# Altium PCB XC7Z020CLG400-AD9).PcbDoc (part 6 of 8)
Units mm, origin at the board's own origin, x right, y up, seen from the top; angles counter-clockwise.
Board outline 38 x 38 mm, 14 copper layers (Top Layer, GND02, ART03, PWR04, ART05, GND06, ART07, ART08, PWR09, ART10, GND11, ART12, PWR13, Bottom Layer); 276 components, 302 nets, 1684 pads, 1576 vias.
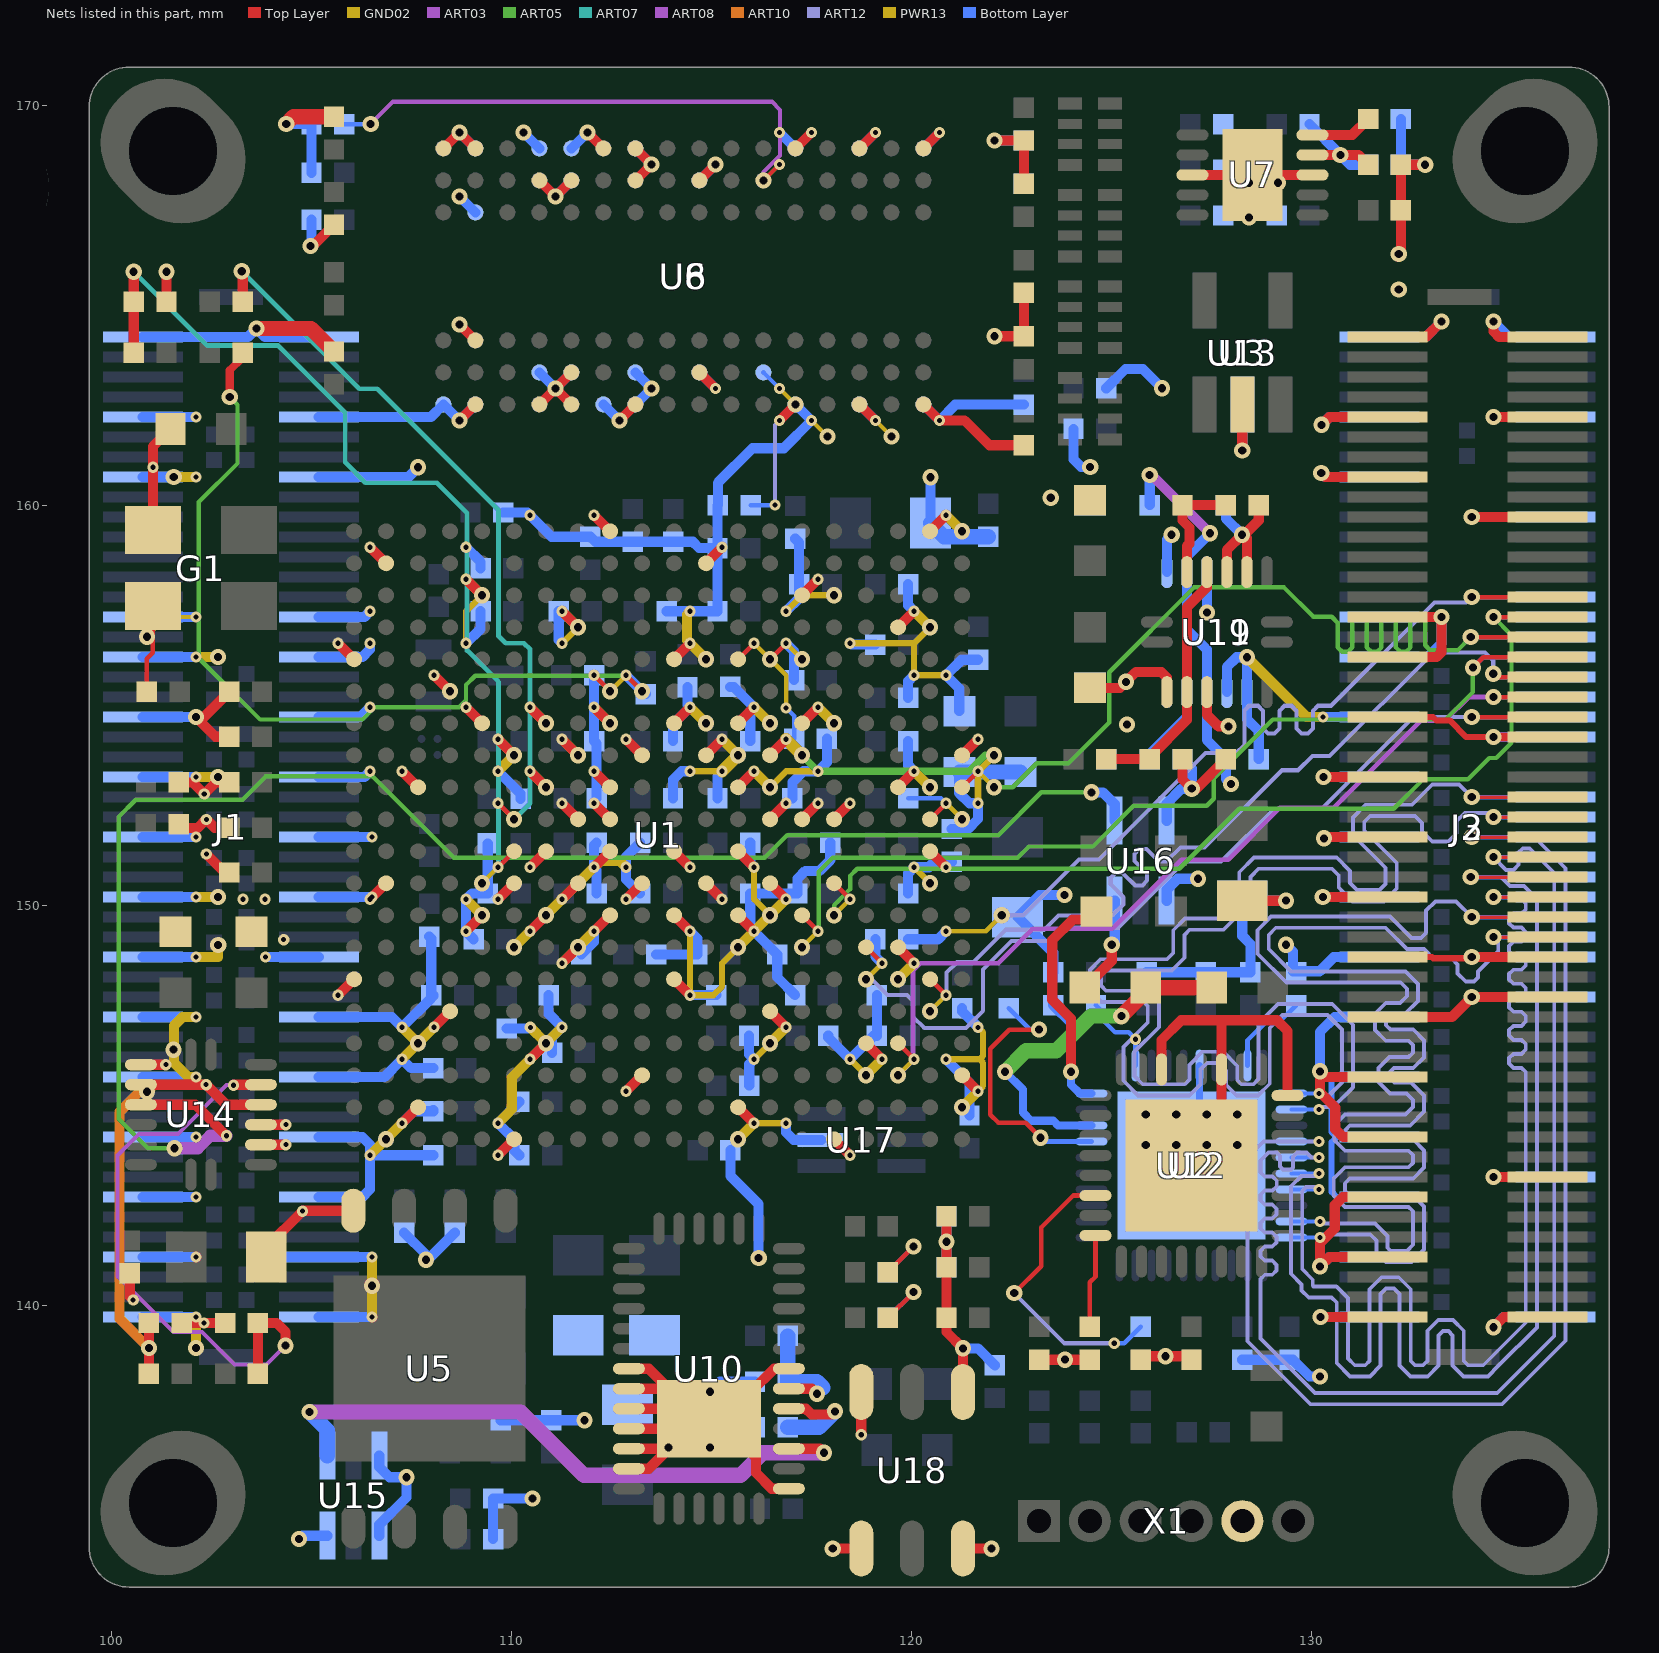
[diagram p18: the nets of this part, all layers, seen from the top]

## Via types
v1: diameter 0.406, hole 0.203, GND02 to PWR13, 466 vias
v2: diameter 0.279, hole 0.127, Top Layer to GND02, tented top, 373 vias
v3: diameter 0.406, hole 0.203, Top Layer to Bottom Layer, 324 vias
v4: diameter 0.279, hole 0.127, PWR13 to Bottom Layer, 207 vias
v5: diameter 0.279, hole 0.127, Top Layer to ART03, tented top, 41 vias
v6: diameter 0.279, hole 0.127, Top Layer to ART03, 40 vias
v7: diameter 0.279, hole 0.127, PWR13 to Bottom Layer, tented bottom, 39 vias
v8: diameter 0.279, hole 0.127, ART12 to Bottom Layer, 30 vias
v9: diameter 0.279, hole 0.127, Top Layer to GND02, 20 vias
v10: diameter 0.406, hole 0.203, Top Layer to Bottom Layer, tented both sides, 16 vias
v11: diameter 0.406, hole 0.203, ART03 to ART12, 11 vias
v12: diameter 0.406, hole 0.203, Top Layer to Bottom Layer, tented top, 9 vias

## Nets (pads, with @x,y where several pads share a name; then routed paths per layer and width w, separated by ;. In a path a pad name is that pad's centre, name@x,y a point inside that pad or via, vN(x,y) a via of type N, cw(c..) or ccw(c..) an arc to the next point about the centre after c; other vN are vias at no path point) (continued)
GND: C2.2 C3.2 C4.2 C5.2 C6.2 C7.2 C8.2 C9.2 C12.2 C13.2 C14.2 C15.2 C16.2 C17.2 C18.2 C19.2 C20.2 C21.2 C22.2 C23.2 C24.1 C25.1 C26.1 C27.1 C28.1 C29.1 C30.2 C31.2 C32.2 C33.2 C37.2 C38.2 C39.2 C40.2 C41.2 C42.2 C43.2 C44.2 C45.2 C46.2 C47.2 C48.2 C49.2 C50.2 C51.2 C52.2 C53.2 C54.2 C55.2 C56.2 C57.2 C58.2 C59.2 C60.2 C61.2 C62.2 C63.2 C64.2 C65.2 C66.2 C67.2 C68.2 C69.2 C70.2 C71.2 C72.2 C73.2 C74.2 C75.2 C76.2 C77.2 C78.2 C79.2 C80.2 C81.2 C93.2 C94.2 C96.1 C97.2 C99.1 C101.2 C102.2 C111.2 C112.2 C113.2 C114.2 C115.2 C116.2 C117.2 C118.2 C119.2 C120.2 C121.2 C122.2 C123.2 C124.2 C125.2 C126.2 C128.2 C129.2 C130.2 C131.2 C132.2 C133.2 C134.2 C135.2 C136.2 C137.2 C138.2 C139.2 C140.2 C144.1 C145.1 C147.2 C148.2 C213.2 C248.1 C249.1 C250.1 C254.2 DONE.2 G1.2 J1.1 J1.5 J1.8 J1.15 J1.17 J1.20 J1.23 J1.26 J1.29 J1.32 J1.35 J1.38 J1.41 J1.44 J1.47 J1.50 J1.51 J1.55 J1.58 J1.65 J1.67 J1.70 J1.73 J1.76 J1.79 J1.82 J1.85 J1.88 J1.91 J1.94 J1.97 J1.100 J2.1 J2.8 J2.17 J2.19 J2.30 J2.41 J2.46 J2.50 J2.51 J2.54 J2.57 J2.60 J2.63 J2.66 J2.69 J2.72 J2.75 J2.78 J2.81 J2.84 J2.86 J2.93 J2.96 J2.100 J3.1 J3.8 J3.17 J3.19 J3.30 J3.41 J3.46 J3.50 J3.51 J3.54 J3.57 J3.60 J3.63 J3.66 J3.69 J3.72 J3.75 J3.78 J3.81 J3.84 J3.86 J3.93 J3.96 J3.100 R1.2 R2.2 R4.2 R8.2 R9.2 R12.2 R15.2 R17.2 R19.2 R20.2 R21.2 R22.2 R26.2 R42.1 R45.2 R52.1 R53.1 R54.1 R55.1 R57.1 R61.2 R64.2 R66.2 R67.2 R68.2 R70.1 R124.1 R135.1 R137.2 R138.2 U1.A8 U1.A18 U1.B1 U1.B11 U1.C4 U1.C9 U1.C14 U1.D17 U1.E10 U1.E20 U1.F3 U1.F7 U1.F10 U1.G10 U1.G12 U1.G16 U1.H7 U1.H9 U1.H11 U1.H13 U1.H19 U1.J2 U1.J8 U1.J12 U1.K5 U1.K7 U1.K11 U1.K13 U1.K15 U1.L8 U1.L12 U1.L18 U1.M1 U1.M7 U1.M9 U1.M10 U1.M11 U1.M13 U1.N4 U1.N8 U1.N10 U1.N12 U1.N14 U1.P7 U1.P9 U1.P11 U1.P13 U1.P17 U1.R8 U1.R12 U1.R20 U1.T3 U1.T7 U1.T13 U1.U6 U1.U16 U1.V9 U1.V19 U1.W2 U1.W12 U1.Y5 U1.Y15 U2.36 U2.41 U3.2 U5.4 U6.A9 U6.B1 U6.B3 U6.B9 U6.D1 U6.D8 U6.E1 U6.E2 U6.E8 U6.F9 U6.G1 U6.G8 U6.G9 U6.J2 U6.J8 U6.M1 U6.M9 U6.P1 U6.P9 U6.T1 U6.T9 U7.3 U7.8 U7.P U8.A9 U8.B1 U8.B3 U8.B9 U8.D1 U8.D8 U8.E1 U8.E2 U8.E8 U8.F9 U8.G1 U8.G8 U8.G9 U8.J2 U8.J8 U8.M1 U8.M9 U8.P1 U8.P9 U8.T1 U8.T9 U10.13 U10.14 U10.15 U10.16 U10.17 U10.18 U10.26 U10.32 U10.39 U11.2 U11.3 U11.9 U12.8 U12.11 U12.14 U12.33 U13.2 U14.2 U14.3 U14.9 U15.3 U15.4 U15.6 U16.3 U16.4 U16.6 U17.2 U18.1 U18.3 U18.4 U18.6 U19.2 U19.3 U19.9 X1.5 | length 463.8
  Top Layer w0.152: J3.69@131.9,148.719 133.018,148.719 133.045,148.692 133.979,148.692 v3(134.007,148.719) ; J3.81@131.9,154.719 133.037,154.719 133.121,154.635 133.452,154.635 133.868,154.219 v3(134.548,154.219)
  Top Layer w0.229: v3(134.548,154.219) J3.30@135.9,154.219
  Top Layer w0.254: C139.2@100.457,140.814 100.457,140.235 v9(100.543,140.149) ; U14.9@100.735,146.03 v9(101.358,146.03) ; G1.2@101.035,159.395 v9(101.035,160.966) 101.035,161.485 C38.2@101.475,161.925 ; DONE.2@101.375,165.1 v3(101.375,165.852) ; C9.2@101.683,151.943 102.151,151.943 v2(102.37,152.163) 102.579,151.954 C148.2@102.943,151.954 C148.2@102.993,151.954 ; C30.2@101.683,153.086 102.032,153.086 v2(102.32,152.798) 102.608,153.086 C32.2@102.943,153.086 ; C140.2@101.756,139.573 v9(102.311,139.573) R12.2@102.841,139.573 ; v2(102.37,151.298) 102.833,150.835 C37.2@102.943,150.835 ; C8.2@102.943,154.229 102.601,154.229 v3(102.111,154.719) 102.309,154.719 C46.2@102.943,155.353 ; U14.2@103.735,144.03 v9(104.358,144.03) ; U14.3@103.735,144.53 v9(104.358,144.53) ; C138.2@103.87,141.224 103.87,141.462 v9(104.775,142.367) 104.788,142.38 U5.4@106.045,142.38 ; v3(104.978,166.497) 105.033,166.497 C55.2@105.562,167.026 ; v2(105.665,147.765) U1.Y15@106.065,148.165 ; v2(105.665,156.565) U1.Y5@106.065,156.165 ; v2(106.465,150.165) U1.W12@106.865,150.565 ; v2(106.465,158.965) U1.W2@106.865,158.565 ; v4(107.265,144.565) U1.V19@107.665,144.965 ; v2(107.265,153.365) U1.V9@107.665,152.965 ; v2(108.065,146.965) U1.U16@108.465,147.365 ; v2(108.065,155.765) v1(108.465,155.365) ; U8.A9@108.3,168.935 v3(108.7,169.335) U8.B9@109.1,168.935 ; v3(108.7,162.135) U8.B1@109.1,162.535 ; v3(108.7,164.535) U8.B3@109.1,164.135 ; v2(108.865,149.365) v1(109.265,149.765) ; v2(108.865,154.965) U1.T7@109.265,154.565 ; v2(108.865,158.165) v1(109.265,157.765) ; v2(109.665,143.765) U1.R20@110.065,144.165 ; v2(109.665,150.165) U1.R12@110.065,150.565 ; v2(109.665,154.165) v1(110.065,153.765) ; v2(110.465,146.165) v1(110.865,146.565) ; v2(110.465,149.365) v1(110.865,149.765) ; v2(110.465,150.965) U1.P11@110.865,151.365 ; v2(110.465,153.365) v1(110.865,152.965) ; v2(110.465,154.965) v1(110.865,154.565) ; U8.D1@110.7,162.535 v3(111.1,162.935) ; U8.D8@110.7,168.135 v3(111.1,167.735) U8.E8@111.5,168.135 ; v2(111.265,148.565) v1(111.665,148.965) ; v2(111.265,150.165) U1.N12@111.665,150.565 ; v2(111.265,152.565) U1.N10@111.665,152.165 ; v2(111.265,154.165) v1(111.665,153.765) ; v2(111.265,157.365) v1(111.665,156.965) ; U8.E1@111.5,162.535 v3(111.1,162.935) ; U8.E2@111.5,163.335 v3(111.1,162.935) ; v3(111.9,169.335) U8.F9@112.3,168.935 ; v4(112.065,149.365) U1.M13@112.465,149.765 ; v4(112.065,150.965) U1.M11@112.465,151.365 ; v2(112.065,152.565) U1.M10@112.465,152.165 ; v2(112.065,153.365) U1.M9@112.465,152.965 ; v4(112.065,154.965) v1(112.465,154.565) ; v2(112.065,159.765) U1.M1@112.465,159.365 ; v3(112.7,162.135) U8.G1@113.1,162.535 ; v2(112.865,145.365) U1.L18@113.265,145.765 ; v2(112.865,150.165) U1.L12@113.265,150.565 ; v2(112.865,154.165) U1.L8@113.265,153.765 ; U10.18@112.935,135.93 113.432,135.93 113.932,136.43 U10.17@112.935,136.43 ; U10.16@112.935,136.93 U10.39@114.445,136.93 ; U10.15@112.935,137.43 U10.39@114.445,137.43 ; U10.14@112.935,137.93 113.93,137.93 113.43,138.43 U10.13@112.935,138.43 ; U8.G8@113.1,168.135 v3(113.5,168.535) U8.G9@113.1,168.935 ; U1.K15@114.065,148.165 v2(114.465,147.765) ; U1.K13@114.065,149.765 v2(114.465,149.365) ; U1.K11@114.065,151.365 v2(114.465,150.965) ; U1.K7@114.065,154.565 v2(114.465,154.965) ; U1.K5@114.065,156.165 v2(114.465,156.565) ; U8.J2@114.7,163.335 v2(115.1,162.935) ; U8.J8@114.7,168.135 v3(115.1,168.535) ; U1.J12@114.865,150.565 v2(115.265,150.165) ; U1.J8@114.865,153.765 v2(115.265,154.165) ; U1.J2@114.865,158.565 v2(115.265,158.965) ; U10.39@114.935,137.175 115.142,137.175 116.116,136.201 116.116,135.82 116.506,135.43 U10.26@116.935,135.43 ; U1.H19@115.665,144.965 v2(116.065,144.565) ; U1.H13@115.665,149.765 v2(116.065,149.365) ; U1.H11@115.665,151.365 v2(116.065,150.965) ; U1.H9@115.665,152.965 v2(116.065,153.365) ; U1.H7@115.665,154.565 v2(116.065,154.965) ; U10.39@115.989,137.852 116.567,138.43 U10.32@116.935,138.43 ; U1.G16@116.465,147.365 v2(116.865,146.965) ; U1.G12@116.465,150.565 v2(116.865,150.165) ; U1.G10@116.465,152.165 v2(116.865,152.565) ; v2(116.7,162.135) U8.M1@117.1,162.535 U8.M1@117.1,162.485 ; U8.M9@117.1,168.935 v2(117.5,169.335) ; U1.F10@117.265,152.165 v2(117.665,152.565) ; U1.F7@117.265,154.565 v2(117.665,154.965) ; U1.F3@117.265,157.765 v2(117.665,158.165) ; v3(118.031,133.931) U18.4@118.745,133.931 ; U1.E20@118.065,144.165 v2(118.465,143.765) ; U1.E10@118.065,152.165 v2(118.465,152.565) ; U8.P1@118.7,162.535 v2(119.1,162.135) ; U8.P9@118.7,168.935 v2(119.1,169.335) ; v9(118.745,136.779) U18.3@118.745,137.849 ; U1.D17@118.865,146.565 v2(119.265,146.165) ; U1.C14@119.665,148.965 v4(120.065,148.565) ; U1.C9@119.665,152.965 v2(120.065,153.365) ; U1.C4@119.665,156.965 v2(120.065,157.365) ; U8.T1@120.3,162.535 v2(120.7,162.135) 121.329,162.135 121.949,161.515 C60.2@122.809,161.515 ; U8.T9@120.3,168.935 v2(120.7,169.335) ; U1.B11@120.465,151.365 v2(120.865,150.965) ; U1.B1@120.465,159.365 v2(120.865,159.765) ; C254.2@120.875,142.24 v3(120.875,141.602) R1.2@120.875,140.97 C25.1@120.875,139.7 120.875,139.348 v3(121.285,138.938) U18.1@121.285,137.849 ; U1.A18@121.265,145.765 v2(121.665,145.365) ; U1.A8@121.265,153.765 v2(121.665,154.165) ; U18.6@121.285,133.931 v3(121.999,133.931) ; v3(122.076,164.24) C56.2@122.809,164.24 C57.2@122.809,165.325 ; v3(122.076,169.135) C59.2@122.809,169.135 C58.2@122.809,168.05 ; R137.2@123.19,138.655 v3(123.837,138.655) R135.1@124.46,138.655 ; C145.1@124.335,147.955 125.006,148.626 v3(125.006,149.028) ; C78.2@124.46,155.45 125.211,155.45 125.61,155.849 126.245,155.849 126.385,155.709 U19.9@126.385,155.345 ; C248.1@125.73,138.655 125.816,138.741 v3(126.352,138.741) 126.914,138.741 C250.1@127,138.655 ; U12.14@126.25,145.91 126.25,146.646 126.746,147.142 127.762,147.142 ; C81.2@126.775,153.67 126.775,153.16 127.007,152.928 127.118,152.928 C80.2@127.86,153.67 ; U12.33@127,143.51 127.75,144.26 U12.11@127.75,145.91 127.75,147.13 127.762,147.142 ; U7.8@127.024,168.275 U7.P@128.524,168.275 U7.3@130.024,168.275 ; U19.3@127.885,158.345 127.885,158.897 v3(128.266,159.278) v3@128.308,159.278 ; C79.2@128.27,150.13 v3(129.365,150.13) ; v3(128.27,161.385) U3.2@128.27,162.53 ; U19.2@128.385,158.345 128.385,159.201 v3@128.308,159.278 ; R26.2@128.68,160.02 128.68,159.643 128.315,159.278 v3@128.308,159.278 ; U12.8@129.4,145.26 129.4,146.876 129.134,147.142 127.762,147.142 ; v10(130.224,139.719) J3.51@131.9,139.719 ; v3(130.251,162.027) 130.444,162.219 J3.96@131.9,162.219 ; v3(130.284,150.219) J3.72@131.9,150.219 ; v3(130.301,153.219) J3.78@131.9,153.219 ; v3(130.314,151.689) 130.344,151.719 J3.75@131.9,151.719 ; v3@130.345,160.719 J3.93@131.9,160.719 ; J3.54@131.9,141.219 130.444,141.219 v3(130.213,140.988) 130.213,141.567 130.581,141.935 130.581,142.519 130.781,142.719 J3.57@131.9,142.719 ; J3.60@131.9,144.219 130.792,144.219 130.594,144.417 130.594,144.958 130.213,145.339 v3(130.213,145.864) 130.358,145.719 J3.63@131.9,145.719 ; J3.66@131.9,147.219 133.507,147.219 v3(134.007,147.719) J3.17@135.9,147.719 ; J3.84@131.9,156.219 133.125,156.219 133.248,156.343 v3(133.248,157.219) J3.86@131.9,157.219 ; J3.100@131.9,164.219 132.857,164.219 v10(133.248,164.61) ; v3@132.169,166.233 v3@132.178,166.224 ; v3@132.236,166.309 C97.2@132.236,167.386 C96.1@132.236,168.529 v3(132.842,168.529) ; v3(134.007,148.719) J3.19@135.9,148.719 ; v3(134.007,159.719) J3.41@135.9,159.719 ; v10(134.548,139.465) 134.802,139.719 J3.1@135.9,139.719 ; v3(134.548,143.219) J3.8@135.9,143.219 ; v10(134.548,162.219) J3.46@135.9,162.219 ; v10(134.548,164.61) 134.548,164.359 134.688,164.219 J3.50@135.9,164.219
  Top Layer w0.381: v3(103.624,164.435) 104.986,164.435 C99.1@105.562,163.859 ; v3(104.369,169.545) 104.554,169.73 C69.2@105.562,169.73
  GND02 w0.152: v2(108.865,149.365) v1(109.265,149.765)
  GND02 w0.254: v1(106.865,144.165) v4(107.265,144.565) ; v1(107.665,146.565) v2(108.065,146.965) ; v2(108.865,158.165) v1(109.265,157.765) ; v2(109.665,154.165) v1(110.065,153.765) ; v1(110.065,148.965) v2(110.465,149.365) ; v2(110.465,146.165) v1(110.865,146.565) ; v2(110.465,153.365) v1(110.865,152.965) ; v2(110.465,154.965) v1(110.865,154.565) ; v1(110.865,149.765) v2(111.265,150.165) ; v2(111.265,148.565) v1(111.665,148.965) v4(112.065,149.365) ; v2(111.265,154.165) v1(111.665,153.765) ; v2(111.265,157.365) v1(111.665,156.965) ; v2(115.265,154.165) v1(115.665,153.765) ; v1(115.665,144.165) v2(116.065,144.565) ; v1(115.665,148.965) v2(116.065,149.365) ; v2(116.065,153.365) v1(116.465,152.965) ; v2(116.065,154.965) v1(116.465,154.565) ; v1(116.465,146.565) v2(116.865,146.965) ; v1(116.465,149.765) v2(116.865,150.165) ; v2(117.665,154.965) v1(118.065,154.565) ; v1(118.865,145.765) v2(119.265,146.165) ; v1(119.665,148.165) v4(120.065,148.565) ; v2(120.065,153.365) v1(120.465,152.965) ; v2(120.065,157.365) v1(120.465,156.965) ; v2(120.865,159.765) v1(121.265,159.365) ; v1(121.265,144.965) v2(121.665,145.365)
  PWR13 w0.102: v1(100.885,156.73) 101.375,157.219 v4(102.111,157.219)
  PWR13 w0.114: v7(117.5,162.135) v1(117.9,161.735) ; v2(119.1,162.135) v1(119.5,161.735)
  PWR13 w0.152: v4(108.865,156.565) 108.865,157.365 v1(109.265,157.765) ; v4(111.265,156.565) v1(111.665,156.965) ; v2(114.465,149.365) v2(114.465,147.765) 115.05,147.765 115.265,147.98 115.265,148.565 v1(115.665,148.965) ; v4(114.465,153.365) v4(115.265,153.365) ; v1(115.665,144.165) v2(116.065,144.565) v4(116.865,144.565) ; v4(116.065,146.165) v1(116.465,146.565) ; v2(116.065,150.965) 116.065,150.165 v1(116.465,149.765) ; v1(116.465,152.965) 116.865,153.365 v4(117.665,153.365) ; v4(116.865,157.365) 117.265,157.765 v1(118.065,157.765) ; v4(118.465,146.165) v1(118.865,145.765) ; v4(118.465,156.565) 120.065,156.565 ; v4(120.065,150.965) v1(120.465,150.565) ; v2(120.065,157.365) v1(120.465,156.965) 120.065,156.565 ; v4(120.865,146.165) 121.705,146.165 ; v4(120.865,155.765) v4(120.065,155.765) 120.065,156.565 ; v1(121.265,144.965) 121.793,145.493 121.793,146.077 121.705,146.165 ; v4(121.666,146.964) 121.793,146.837 121.793,146.253 121.705,146.165
  PWR13 w0.254: v1(101.557,160.719) v4(102.111,160.719) ; v4(102.111,139.719) 102.111,138.947 v1(102.114,138.944) ; v4(102.111,145.719) 101.924,145.719 101.559,146.085 101.559,147.007 101.771,147.219 v4(102.111,147.219) ; v4(102.111,148.719) 102.665,148.719 102.667,148.721 v1(102.667,149.022) ; v4(102.111,150.219) v1(102.665,150.219) ; v4(102.111,153.219) v1(102.665,153.219) ; v4(102.111,156.219) v1(102.665,156.219) ; v4(106.465,143.765) v1(106.865,144.165) v4(107.265,144.565) ; v4(106.511,139.719) v1(106.511,140.504) v4(106.511,141.219) ; v4(107.265,146.165) v1(107.665,146.565) v4(107.265,146.965) ; v4(108.865,150.165) v1(109.265,149.765) ; v4(109.665,144.565) 110.007,144.907 110.007,145.707 v1(110.865,146.565) ; v4(109.665,153.365) v1(110.065,153.765) ; v4(110.471,146.964) 110.865,146.571 v1(110.865,146.565) ; v1(110.865,149.765) v4(112.065,150.965) 112.23,151.13 112.7,151.13 v4(112.865,150.965) ; v4@111.221,146.921 v4(111.265,146.965) v1(110.865,146.565) ; v1(111.665,148.965) v4(112.065,149.365) ; v4(112.065,154.965) v1(112.465,154.565) ; v2(114.465,154.965) v1(114.865,154.565) ; v4(114.465,157.365) 114.388,157.288 114.388,156.642 v1(114.865,156.165) ; v1(115.665,148.965) v2(116.065,149.365) v1(116.465,149.765) ; v2(116.065,154.965) v1(116.465,154.565) ; v1(119.665,148.165) v4(120.065,148.565) ; v2(120.065,153.365) v1(120.465,152.965) ; v3(128.385,156.217) 129.883,154.719 v4(130.284,154.719)
  PWR13 w0.305: v4(115.265,153.365) v1(115.665,153.765)
  Bottom Layer w0.114: v3@134.523,154.219 v3(134.548,154.219)
  Bottom Layer w0.152: 130.505,145.618 130.505,144.344 130.63,144.219 ; J2.57@131.7,142.719 130.636,142.719 130.505,142.85 130.505,144.094 130.63,144.219 ; J2.60@131.7,144.219 130.63,144.219
  Bottom Layer w0.178: U2.41@127.2,143.71 U2.36@127.2,146.01
  Bottom Layer w0.229: v10@134.523,139.465 134.777,139.719 J2.1@136.1,139.719
  Bottom Layer w0.254: J1.50@100.782,139.719 v4(102.111,139.719) ; J1.47@100.782,141.219 v4(102.111,141.219) ; J1.44@100.782,142.719 v4(102.111,142.719) ; J1.41@100.782,144.219 v4(102.111,144.219) ; J1.38@100.782,145.719 v4(102.111,145.719) ; J1.35@100.782,147.219 v4(102.111,147.219) ; J1.32@100.782,148.719 v4(102.111,148.719) ; J1.29@100.782,150.219 v4(102.111,150.219) ; J1.26@100.782,151.719 v4(102.111,151.719) ; J1.23@100.782,153.219 v4(102.111,153.219) ; J1.20@100.782,154.719 v3(102.111,154.719) ; J1.17@100.782,156.219 v4(102.111,156.219) ; J1.15@100.782,157.219 v4(102.111,157.219) ; J1.8@100.782,160.719 v4(102.111,160.719) ; J1.5@100.782,162.219 v4(102.111,162.219) ; J1.1@100.782,164.219 103.408,164.219 v3(103.624,164.435) 103.84,164.219 J1.51@105.182,164.219 ; v4(103.848,148.719) J1.82@105.182,148.719 ; v3(104.369,169.545) R66.2@105,169.545 C75.2@105,168.326 ; J1.97@104.376,141.219 J1.97@105.182,141.219 v4(106.511,141.219) ; v3(104.686,134.169) 104.772,134.255 U15.6@105.395,134.255 ; v3(104.978,166.497) 105,166.519 C102.2@105,167.157 ; J1.100@105.182,139.719 v4(106.511,139.719) ; J1.94@105.182,142.719 106.27,142.719 106.465,142.914 v4(106.465,143.765) ; J1.91@105.182,144.219 106.276,144.219 106.465,144.03 v4(106.465,143.765) ; J1.88@105.182,145.719 106.819,145.719 v4(107.265,146.165) 107.487,145.943 C23.2@108.045,145.943 ; J1.85@105.182,147.219 107.011,147.219 v4(107.265,146.965) 107.994,147.694 C22.2@107.994,147.765 107.994,149.184 R124.1@107.946,149.233 ; J1.79@105.182,150.219 v4(106.511,150.219) ; J1.76@105.182,151.719 v4(106.511,151.719) ; J1.73@105.182,153.219 106.319,153.219 v4(106.465,153.365) ; J1.70@105.182,154.719 106.219,154.719 v4(106.465,154.965) ; J1.67@105.182,156.219 106.271,156.219 106.465,156.413 v4(106.465,156.565) ; J1.65@105.182,157.219 106.319,157.219 v4(106.465,157.365) ; J1.58@105.182,160.719 107.418,160.719 v3(107.665,160.966) ; J1.55@105.182,162.219 107.984,162.219 U6.A9@108.3,162.535 v3(108.7,162.135) U6.B9@109.1,162.535 ; U15.4@106.695,134.255 106.695,134.527 107.376,135.208 v3(107.376,135.716) 106.949,135.716 106.695,135.97 U15.3@106.695,136.255 ; v4(107.265,144.565) 107.564,144.864 C19.2@108.012,144.864 ; R55.1@107.315,141.83 v3@107.861,141.284 ; v3(107.861,141.154) 107.909,141.154 R54.1@108.585,141.83 ; C21.2@108.045,143.765 v4(106.465,143.765) ; C19.2@108.045,144.864 C19.2@108.012,144.864 ; C19.2@108.045,144.897 C19.2@108.012,144.864 ; C22.2@108.045,147.745 C22.2@108.045,147.765 ; v3(108.7,167.735) U6.B3@109.1,167.335 ; v3(108.7,169.335) U6.B1@109.1,168.935 ; v4@108.849,158.965 v4(108.865,158.965) 109.229,158.601 C62.2@109.229,158.437 ; v4(108.865,156.565) 109.229,156.929 C6.2@109.229,157.365 ; C45.2@109.054,149.164 108.865,149.353 v4(108.865,150.165) 109.009,150.309 C43.2@109.407,150.309 C33.2@109.407,151.562 ; R57.1@109.541,134.169 R53.1@109.541,135.185 v3(110.528,135.185) ; v4(109.665,153.365) 110.227,152.803 C31.2@110.227,152.678 ; C24.1@109.728,137.14 C48.2@110.998,137.14 v3(111.826,137.14) ; C68.2@109.795,159.834 110.396,159.834 v4(110.465,159.765) 111.002,159.228 R68.2@111.973,159.228 112.099,159.102 C64.2@113.03,159.102 C74.2@114.046,159.102 114.532,159.102 114.689,158.945 C71.2@115.151,158.945 ; C51.2@109.88,146.935 110.442,146.935 v4(110.471,146.964) ; C20.2@110.195,143.765 110.068,143.892 110.068,144.162 v4(109.665,144.565) 109.665,144.572 C18.2@110.195,145.102 ; v3(110.3,169.335) U6.D1@110.7,168.935 ; U6.D8@110.7,163.335 v3(111.1,162.935) U6.E8@111.5,163.335 ; C13.2@110.928,147.765 110.928,147.302 v4(111.265,146.965) 111.015,146.715 C41.2@111.015,146.325 ; v3(111.1,167.735) U6.E2@111.5,168.135 ; C5.2@111.182,157.365 111.182,156.648 v4(111.265,156.565) ; U6.E1@111.5,168.935 v3(111.9,169.335) ; C47.2@111.748,148.785 112.065,149.102 v4(112.065,149.365) ; C66.2@112.065,155.765 v4(112.065,154.965) C112.2@112.065,154.119 112.129,154.055 C121.2@112.129,152.692 ; C120.2@112.129,150.309 112.129,150.901 v4(112.065,150.965) 112.065,151.515 C124.2@112.129,151.579 ; U6.F9@112.3,162.535 v3(112.7,162.135) ; U6.G9@113.1,162.535 v3(113.5,162.935) U6.G8@113.1,163.335 ; U6.G1@113.1,168.935 v3(113.5,168.535) ; C123.2@113.217,150.309 112.865,150.661 112.865,151.227 C122.2@113.217,151.579 ; C44.2@113.618,148.785 C72.2@114.644,148.785 114.644,149.186 v2(114.465,149.365) ; C61.2@113.878,157.365 C70.2@115.151,157.365 C71.2@115.151,158.945 ; C119.2@114.037,152.692 114.037,153.153 114.249,153.365 v4(114.465,153.365) ; C113.2@114.037,154.119 114.037,154.537 v2(114.465,154.965) 114.402,155.028 C76.2@114.402,155.466 ; v2(114.465,147.765) 114.469,147.769 C39.2@115.119,147.769 ; U6.J8@114.7,163.335 v2(115.1,162.935) ; U6.J2@114.7,168.135 v3(115.1,168.535) ; v3(114.959,136.455) 115.579,136.455 C135.2@116.087,136.963 ; v3(114.959,137.852) 115.213,138.106 R9.2@116.087,138.106 ; C118.2@115.151,152.692 115.151,153.251 v4(115.265,153.365) ; C49.2@115.468,155.473 115.557,155.473 v2(116.065,154.965) 115.971,154.871 C54.2@115.971,154.119 ; C14.2@115.472,143.891 115.472,143.252 116.18,142.545 v3(116.18,141.199) ; C40.2@115.939,146.753 115.939,146.291 v4(116.065,146.165) 115.943,146.043 C12.2@115.943,145.507 ; C117.2@115.971,151.579 115.971,151.059 v2(116.065,150.965) ; v7(116.7,169.335) U6.M1@117.1,168.935 ; v4(116.865,144.565) 116.865,144.337 117.058,144.145 U17.2@117.745,144.145 ; v4(116.865,157.365) 117.192,157.692 C67.2@117.192,158.045 117.192,159.08 C7.2@117.094,159.178 ; R45.2@117.024,152.692 117.024,153.092 117.297,153.365 v4(117.665,153.365) 117.885,153.585 R70.1@117.885,154.178 ; C17.2@117.09,147.769 116.662,148.197 116.662,148.209 116.643,148.228 C42.2@116.643,148.785 116.065,149.363 v2(116.065,149.365) 115.971,149.459 C114.2@115.971,150.309 C213.2@117.151,150.309 117.151,150.679 117.348,150.876 117.704,150.876 117.971,151.143 C115.2@117.971,151.579 ; U6.M9@117.1,162.535 v7(117.5,162.135) 116.807,161.442 116.027,161.442 115.16,160.575 R61.2@115.16,160.02 115.151,160.011 C71.2@115.151,158.945 ; C15.2@117.92,146.753 117.92,146.71 v4(118.465,146.165) 119.053,146.753 R20.2@119.136,146.753 C16.2@119.136,147.769 ; v4(118.465,156.565) 118.498,156.532 R67.2@119.097,156.532 ; U6.P9@118.7,162.535 v2(119.1,162.135) ; U6.P1@118.7,168.935 v2(119.1,169.335) ; R22.2@119.917,150.309 119.917,150.817 v4(120.065,150.965) 120.434,150.965 120.57,151.101 C126.2@121.006,151.101 ; R42.1@119.917,154.119 119.917,153.513 v2(120.065,153.365) ; R52.1@119.917,155.199 119.917,155.617 v4(120.065,155.765) ; C50.2@119.917,158.045 119.917,157.513 v2(120.065,157.365) ; U6.T9@120.3,162.535 v2(120.7,162.135) 121.096,162.531 C73.2@122.809,162.531 ; U6.T1@120.3,168.935 v2(120.7,169.335) ; C53.2@120.475,159.569 v3(120.475,160.715) ; v4(120.865,146.165) 121.451,145.579 R4.2@121.451,144.761 ; R2.2@120.875,140.97 v3(120.875,141.602) C144.1@120.875,142.24 ; C125.2@121.196,154.868 121.196,155.434 v4(120.865,155.765) 121.255,156.155 C63.2@121.665,156.155 ; R19.2@121.265,147.444 121.265,147.365 v4(121.666,146.964) ; v3(121.285,138.938) 121.663,138.938 C249.1@122.085,138.516 ; v3(122.076,169.135) C4.2@122.809,169.135 C52.2@122.809,168.05 ; C28.1@123.546,148.34 123.546,148.827 C116.2@122.653,149.72 123.206,150.273 v3(123.825,150.273) ; C147.2@124.05,161.925 124.05,161.167 124.245,160.972 v3(124.467,160.972) ; C65.2@124.87,162.941 125.353,163.424 125.781,163.424 v3(126.263,162.941) ; v3(125.006,149.028) 125.08,149.102 U16.6@125.08,150.13 ; R15.2@125.882,148.34 R17.2@127.356,148.34 C26.1@128.473,148.34 128.473,149.047 128.27,149.25 C132.2@128.27,150.13 v3(129.365,150.13) ; U16.4@126.38,150.13 126.38,150.402 126.657,150.679 v3(127.165,150.679) ; U16.3@126.38,152.13 126.38,152.561 126.747,152.928 127.007,152.928 127.007,153.438 R8.2@126.775,153.67 ; U11.9@126.385,158.345 126.385,159.158 v3(126.505,159.278) ; U2.41@127,143.51 U2.41@127.2,143.71 ; C133.2@127.86,160.02 127.86,159.684 v3(128.266,159.278) ; U11.3@127.885,155.345 127.885,155.971 128.131,156.217 v3(128.385,156.217) U11.2@128.385,155.345 128.385,154.666 128.68,154.371 C134.2@128.68,153.67 ; C29.1@128.27,138.655 C27.1@129.451,138.655 129.532,138.655 129.954,138.233 v3(130.213,138.233) ; v3(128.27,161.385) U13.2@128.27,162.53 ; v3(129.365,149.028) 129.54,148.853 129.54,148.365 130.204,148.365 130.558,148.719 J2.69@131.7,148.719 ; v3(130.213,140.988) 130.444,141.219 J2.54@131.7,141.219 ; v10(130.224,139.719) J2.51@131.9,139.719 ; v3(130.243,160.821) 130.345,160.719 J2.93@131.7,160.719 ; v3(130.251,162.027) 130.444,162.219 J2.96@131.7,162.219 ; v3(130.284,150.219) J2.72@131.7,150.219 ; v4(130.284,154.719) J2.81@131.7,154.719 ; v3(130.301,153.219) J2.78@131.7,153.219 ; v3(130.314,151.689) 130.344,151.719 J2.75@131.7,151.719 ; J2.63@131.7,145.719 130.358,145.719 v3(130.213,145.864) 130.213,146.85 130.582,147.219 J2.66@131.7,147.219 ; J2.84@131.7,156.219 132.902,156.219 133.248,156.566 v3(133.248,157.219) J2.86@131.7,157.219 ; J2.100@131.7,164.219 132.857,164.219 v10(133.248,164.61) ; R138.2@132.236,169.672 R64.2@132.236,168.529 v3(132.842,168.529) ; v3(134.007,147.719) J2.17@136.1,147.719 ; v3(134.007,148.719) J2.19@136.1,148.719 ; v3(134.007,159.719) J2.41@136.1,159.719 ; v3@134.523,143.219 J2.8@136.1,143.219 ; v3(134.548,154.219) J2.30@136.1,154.219 ; v10(134.548,162.219) J2.46@136.1,162.219 ; v10(134.548,164.61) 134.939,164.219 J2.50@136.1,164.219
  Bottom Layer w0.381: C53.2@120.475,159.569 120.815,159.229 C101.2@121.92,159.229
  other v1: 101.549,146.406
  other v2: 107.265,144.565 120.065,148.565 112.065,149.365 112.065,150.965 112.065,154.965
  other v3: 113.93,136.455 127.007,152.93 125.387,154.534 123.482,160.204 132.181,165.411 132.181,166.3 128.435,167.208 128.435,168.078 129.159,168.078
  other v4: 114.465,147.765 114.465,149.365 116.065,149.365 116.065,150.965 120.065,153.365 114.465,154.965 116.065,154.965 120.065,157.365
  other v7: 119.1,162.135 120.7,162.135 115.1,162.935 119.1,169.335 120.7,169.335
  other v9: 104.305,149.155 103.289,150.165 103.835,150.165
  other v10: 125.362,155.601
  other v12: 125.857,144.018 126.619,144.018 127.381,144.018 128.143,144.018 125.857,144.78 126.619,144.78 127.381,144.78 128.143,144.78
MDIN0: J2.26 J3.26 U2.2 | length 34.8
  Top Layer w0.089: v3(134.548,152.219) J3.26@135.9,152.219
  ART12 w0.097: v8(130.188,144.91) 130.248,144.97 130.545,144.97 131.039,145.464 131.039,147.029 130.519,147.549 129.159,147.549 128.676,147.066 128.676,145.669 128.549,145.542 128.245,145.542 128.143,145.644 128.143,145.999 127.787,146.355 127.279,146.355 126.949,146.025 126.949,145.658 126.833,145.542 125.781,145.542 125.578,145.745 125.578,146.355 126.187,146.964 126.187,147.614 125.922,147.879 124.866,147.879 124.739,148.006 124.739,148.285 124.841,148.387 126.506,148.387 126.822,148.703 126.822,149.276 126.949,149.403 127.802,149.403 128.473,150.074 128.473,150.724 128.676,150.927 130.516,150.927 130.683,150.76 130.683,150.455 131.024,150.114 131.815,150.114 132.131,150.43 132.131,151.068 131.318,151.881 131.318,152.095 131.47,152.248 132.588,152.248 132.766,152.07 132.766,151.867 133.02,151.613 133.426,151.613 133.629,151.816 133.629,152.121 133.833,152.324 134.444,152.324 v3(134.548,152.219)
  Bottom Layer w0.089: U2.2@129.5,144.91 v8(130.188,144.91) v8@130.213,144.91
  Bottom Layer w0.114: v3(134.548,152.219) J2.26@136.1,152.219
MDIN1: J2.24 J3.24 U2.5 | length 34.9
  Top Layer w0.089: v3(134.548,151.219) J3.24@135.9,151.219
  ART12 w0.097: v8(130.188,143.71) 130,143.71 129.88,143.831 129.642,143.831 129.54,143.729 129.54,143.459 129.489,143.408 129.286,143.408 129.21,143.485 129.21,143.754 129.134,143.831 128.921,143.831 128.727,143.637 128.727,143.338 128.832,143.233 129.027,143.233 129.133,143.128 129.133,142.988 129.027,142.883 128.832,142.883 128.727,142.777 128.727,142.637 128.832,142.532 129.02,142.532 129.125,142.427 129.125,142.287 129.02,142.182 128.832,142.182 128.727,142.076 128.727,141.936 128.832,141.831 129.02,141.831 129.125,141.726 129.125,141.586 129.02,141.481 128.832,141.481 128.727,141.375 128.727,141.235 128.832,141.13 129.02,141.13 129.125,141.025 129.125,140.885 129.02,140.779 128.832,140.779 128.727,140.674 128.727,139.181 130.088,137.82 134.645,137.82 136.068,139.243 136.068,150.825 135.458,151.435 135.28,151.435 135.179,151.333 135.179,151.028 135.052,150.901 134.866,150.901 v3(134.548,151.219)
  Bottom Layer w0.089: U2.5@129.5,143.71 v8(130.188,143.71)
  Bottom Layer w0.114: v3@134.523,151.219 v3(134.548,151.219) J2.24@136.1,151.219
MDIN2: J2.22 J3.22 U2.7 | length 34.7
  Top Layer w0.089: v3(134.548,150.219) J3.22@135.9,150.219
  ART12 w0.097: 129.794,142.9 129.769,142.875 ; v8(130.188,142.91) 130.127,142.97 129.864,142.97 129.769,142.875 ; v3(134.548,150.219) 135.201,150.219 135.357,150.063 135.357,149.911 135.251,149.806 135.046,149.806 134.941,149.7 134.941,149.56 135.046,149.455 135.251,149.455 135.357,149.35 135.357,149.21 135.251,149.105 135.046,149.105 134.941,148.999 134.941,148.859 135.046,148.754 135.251,148.754 135.357,148.649 135.357,148.509 135.251,148.404 135.046,148.404 134.941,148.298 134.941,148.158 135.046,148.053 135.251,148.053 135.357,147.948 135.357,147.808 135.251,147.703 135.046,147.703 134.941,147.597 134.941,147.457 135.046,147.352 135.251,147.352 135.357,147.247 135.357,147.107 135.251,147.001 135.046,147.001 134.941,146.896 134.941,146.756 135.046,146.651 135.251,146.651 135.357,146.546 135.357,146.406 135.251,146.3 135.046,146.3 134.941,146.195 134.941,146.055 135.046,145.95 135.251,145.95 135.357,145.845 135.357,139.579 134.293,138.515 133.915,138.515 133.808,138.622 133.808,139.378 133.537,139.649 133.169,139.649 132.898,139.378 132.898,138.622 132.791,138.515 132.588,138.515 132.481,138.622 132.481,140.417 132.182,140.716 131.75,140.716 131.451,140.417 131.451,138.622 131.343,138.515 131.081,138.515 130.912,138.684 130.912,140.197 130.621,140.487 130.048,140.487 130.033,140.503 130.033,140.654 129.769,140.918 129.769,142.875
  Bottom Layer w0.089: U2.7@129.5,142.91 v8(130.188,142.91) v8@130.213,142.91
  Bottom Layer w0.114: v3@134.523,150.219 v3(134.548,150.219) J2.22@136.1,150.219
MDIN3: J2.20 J3.20 U2.10 | length 34.7
  Top Layer w0.089: v3(134.548,149.219) J3.20@135.9,149.219
  ART12 w0.097: v8(130.213,141.71) 130.286,141.783 131.47,141.783 131.623,141.63 131.623,141.337 131.863,141.097 132.501,141.097 132.817,141.413 132.817,142.483 132.546,142.754 130.955,142.754 130.835,142.873 130.835,143.065 130.955,143.185 132.546,143.185 132.817,143.456 132.817,143.887 132.546,144.158 130.955,144.158 130.848,144.265 130.848,144.401 130.955,144.508 132.469,144.508 132.817,144.856 132.817,145.263 132.492,145.587 132.074,145.587 131.953,145.709 131.953,145.833 132.063,145.943 132.546,145.943 132.817,146.214 132.817,146.637 132.546,146.908 131.971,146.908 131.864,147.015 131.864,147.186 131.971,147.293 132.333,147.293 132.664,147.625 132.664,148.045 132.348,148.361 129.489,148.361 128.93,148.92 128.93,149.276 129.108,149.454 131.851,149.454 132.385,148.92 132.817,148.92 133.071,148.666 133.528,148.666 133.655,148.539 133.655,148.311 133.858,148.107 134.061,148.107 134.163,148.209 134.163,148.361 134.671,148.869 134.671,149.097 v3(134.548,149.219)
  Bottom Layer w0.089: U2.10@129.5,141.71 v8(130.213,141.71)
  Bottom Layer w0.114: v3(134.548,149.219) J2.20@136.1,149.219
MDIP0: J2.27 J3.27 U2.1 | length 34.8
  Top Layer w0.089: v3(134.007,152.719) J3.27@135.9,152.719
  ART12 w0.097: v8(130.188,145.31) 130.248,145.25 130.429,145.25 130.759,145.58 130.759,146.914 130.404,147.269 129.275,147.269 128.956,146.95 128.956,145.553 128.665,145.263 128.129,145.263 127.864,145.528 127.864,145.883 127.672,146.075 127.395,146.075 127.229,145.909 127.229,145.542 126.949,145.263 125.665,145.263 125.298,145.629 125.298,146.471 125.908,147.08 125.908,147.498 125.806,147.599 124.751,147.599 124.46,147.89 124.46,148.401 124.725,148.666 126.39,148.666 126.543,148.819 126.543,149.392 126.833,149.682 127.686,149.682 128.194,150.19 128.194,150.839 128.561,151.206 130.632,151.206 130.962,150.876 130.962,150.571 131.14,150.393 131.699,150.393 131.851,150.546 131.851,150.952 131.039,151.765 131.039,152.211 131.355,152.527 132.512,152.527 133.02,153.035 133.691,153.035 v3(134.007,152.719)
  Bottom Layer w0.089: U2.1@129.5,145.31 v8(130.188,145.31) v8@130.213,145.31
  Bottom Layer w0.114: v3(134.007,152.719) J2.27@136.1,152.719
MDIP1: J2.25 J3.25 U2.4 | length 35
  Top Layer w0.089: v3(134.007,151.719) J3.25@135.9,151.719
  ART12 w0.097: v8(130.188,144.11) 128.805,144.11 128.397,143.702 128.397,139.116 129.972,137.541 134.761,137.541 136.347,139.127 136.347,150.941 135.569,151.719 v3(134.007,151.719)
  Bottom Layer w0.089: U2.4@129.5,144.11 v8(130.188,144.11) v8@130.213,144.11
  Bottom Layer w0.114: v3(134.007,151.719) J2.25@136.1,151.719
MDIP2: J2.23 J3.23 U2.6 | length 34.8
  Top Layer w0.089: v3@134.007,150.719 J3.23@135.9,150.719
  ART12 w0.097: v8(130.188,143.31) 130.127,143.25 129.748,143.25 129.489,142.991 129.489,140.802 129.753,140.538 129.753,140.387 129.932,140.208 130.505,140.208 130.632,140.081 130.632,138.568 130.965,138.235 131.459,138.235 131.73,138.506 131.73,140.301 131.866,140.437 132.066,140.437 132.201,140.301 132.201,138.506 132.472,138.235 132.907,138.235 133.178,138.506 133.178,139.263 133.285,139.37 133.421,139.37 133.528,139.263 133.528,138.506 133.799,138.235 134.409,138.235 134.679,138.506 135.636,139.463 135.636,150.179 135.316,150.499 134.961,150.499 134.74,150.719 v3(133.982,150.719)
  Bottom Layer w0.089: U2.6@129.5,143.31 v8(130.188,143.31) v8@130.213,143.31
  Bottom Layer w0.114: v3@134.007,150.719 J2.23@136.1,150.719
MDIP3: J2.21 J3.21 U2.9 | length 34.7
  Top Layer w0.089: v3(134.007,149.719) J3.21@135.9,149.719
  ART12 w0.097: v8(130.213,142.11) 130.261,142.062 131.586,142.062 131.902,141.746 131.902,141.453 131.978,141.376 132.385,141.376 132.537,141.529 132.537,142.367 132.43,142.474 130.84,142.474 130.556,142.758 130.556,143.181 130.84,143.464 132.43,143.464 132.537,143.571 132.537,143.771 132.43,143.878 130.84,143.878 130.569,144.149 130.569,144.517 130.84,144.788 132.353,144.788 132.537,144.972 132.537,145.147 132.376,145.308 131.959,145.308 131.674,145.593 131.674,145.948 131.947,146.222 132.43,146.222 132.537,146.329 132.537,146.522 132.43,146.629 131.856,146.629 131.585,146.899 131.585,147.302 131.856,147.573 132.217,147.573 132.385,147.741 132.385,147.93 132.232,148.082 129.373,148.082 128.651,148.804 128.651,149.392 128.992,149.733 131.967,149.733 132.501,149.2 132.74,149.2 132.867,149.327 132.867,149.885 133.096,150.114 133.612,150.114 v3(134.007,149.719) v3@134.019,149.708
  Bottom Layer w0.089: U2.9@129.5,142.11 v8(130.213,142.11)
  Bottom Layer w0.114: v3(134.007,149.719) J2.21@136.1,149.719
MMC-CLK: J2.37 J3.37 R24.2 | length 24.3
  Top Layer w0.114: v3(134.007,157.719) J3.37@135.9,157.719
  ART12 w0.102: v1(122.257,149.765) 122.79,149.765 124.185,151.159 124.693,151.159 127.356,153.822 128.118,153.822 128.321,154.026 128.321,154.889 128.435,155.004 128.659,155.004 128.784,154.878 128.784,154.431 128.91,154.305 129.078,154.305 129.203,154.431 129.203,154.878 129.329,155.004 129.497,155.004 129.623,154.878 129.623,154.431 129.748,154.305 129.916,154.305 130.042,154.431 130.042,154.878 130.167,155.004 130.251,155.004 130.493,155.004 133.071,157.582 133.869,157.582 v3(134.007,157.719)
  PWR13 w0.114: v4(120.865,149.365) 121.857,149.365 v1(122.257,149.765)
  Bottom Layer w0.114: v3(134.007,157.719) J2.37@136.1,157.719
  Bottom Layer w0.254: R24.2@119.917,149.166 120.666,149.166 v4(120.865,149.365)
MMC-CMD: J2.32 J3.32 U1.C17 | length 24.1
  Top Layer w0.114: U1.C17@119.665,146.565 v2(120.065,146.165) ; v3(134.548,155.219) J3.32@135.9,155.219
  GND02 w0.109: v1(119.665,145.765) v2(120.065,146.165)
  ART08 w0.119: v1(119.665,145.765) 120.04,146.14 120.04,148.387 120.218,148.565 122.174,148.565 123.038,149.428 125.019,149.428 126.746,151.155 127.914,151.155 129.21,152.451 130.556,152.451 132.74,154.635 133.35,154.635 133.934,155.219 v3(134.548,155.219)
  Bottom Layer w0.114: v3(134.548,155.219) J2.32@136.1,155.219
MMC-D0: J2.36 J3.36 U1.E12 | length 26.4
  Top Layer w0.114: U1.E12@118.065,150.565 v2(118.465,150.165) ; v3(134.548,157.219) J3.36@135.9,157.219
  ART05 w0.109: v1(118.065,149.765) 118.065,150.018 118.466,150.419 118.466,150.749 118.643,150.927 126.695,150.927 128.194,152.425 132.055,152.425 132.791,153.162 133.909,153.162 134.442,153.695 134.62,153.695 135.001,154.076 135.001,156.767 v3(134.548,157.219)
  GND02 w0.109: v1(118.065,149.765) v2(118.465,150.165)
  Bottom Layer w0.114: v3(134.548,157.219) J2.36@136.1,157.219
MMC-D1: J2.35 J3.35 U1.A9 | length 25.5
  Top Layer w0.114: U1.A9@121.265,152.965 v2(121.665,153.365) ; v3@134.007,156.719 J3.35@135.9,156.719
  ART05 w0.109: v1(122.065,152.965) 122.53,152.965 123.133,153.568 123.927,153.568 124.943,154.584 124.943,155.843 127.063,157.963 129.311,157.963 130.048,157.226 130.505,157.226 130.658,157.074 130.658,156.462 130.767,156.353 130.912,156.353 131.021,156.462 131.021,157.117 131.13,157.226 131.275,157.226 131.384,157.117 131.384,156.462 131.493,156.353 131.638,156.353 131.747,156.462 131.747,157.117 131.856,157.226 132.002,157.226 132.11,157.117 132.11,156.462 132.219,156.353 132.365,156.353 132.474,156.462 132.474,157.117 132.583,157.226 132.74,157.226 132.842,157.124 132.842,156.515 132.969,156.388 133.65,156.388 v3(133.982,156.719) v3@134.007,156.719
  GND02 w0.109: v2(121.665,153.365) v1(122.065,152.965)
  Bottom Layer w0.114: v3@134.007,156.719 J2.35@136.1,156.719
MMC-D2: J2.34 J3.34 U1.F13 | length 26.5
  Top Layer w0.114: U1.F13@117.265,149.765 v2(117.665,149.365) ; v3(134.036,155.956) 134.299,156.219 J3.34@135.9,156.219
  ART05 w0.109: v1(117.265,148.965) 117.678,149.378 117.678,150.851 118.034,151.206 122.657,151.206 122.936,151.486 124.536,151.486 125.552,152.502 127.381,152.502 127.559,152.679 127.559,153.187 129.032,154.661 133.35,154.661 134.036,155.346 v3(134.036,155.956)
  GND02 w0.109: v1(117.265,148.965) v2(117.665,149.365)
  Bottom Layer w0.114: v3(134.036,155.956) 134.299,156.219 J2.34@136.1,156.219
MMC-D3: J2.33 J3.33 U1.B15 | length 24.6
  Top Layer w0.114: U1.B15@120.465,148.165 v2(120.865,147.765) ; v3@134.628,155.719 J3.33@135.9,155.719
  ART12 w0.102: v1(120.465,147.365) 120.879,147.779 120.879,148.336 121.133,148.59 121.539,148.59 122.352,149.403 123.317,149.403 123.673,149.758 125.019,149.758 125.298,150.038 125.298,150.216 124.982,150.532 124.982,150.709 125.101,150.828 125.278,150.828 125.594,150.512 125.772,150.512 125.891,150.63 125.891,150.808 125.575,151.124 125.575,151.302 125.693,151.421 125.871,151.421 126.187,151.105 126.365,151.105 126.721,151.46 127.33,151.46 129.261,153.391 129.667,153.391 130.023,153.746 130.454,153.746 133.045,156.337 134.341,156.337 134.544,156.134 v3(134.544,155.804)
  GND02 w0.109: v1(120.465,147.365) v2(120.865,147.765)
  Bottom Layer w0.114: v3@134.628,155.719 J2.33@136.1,155.719
MMC-SCLK: J2.31 J3.31 R24.1 U1.D14 | length 26.1
  Top Layer w0.114: U1.D14@118.865,148.965 v2(119.265,148.565) ; v3(134.007,154.719) J3.31@135.9,154.719
  ART12 w0.102: v1(118.865,148.165) 119.018,148.165 119.405,147.777 119.888,147.777 120.04,147.625 120.04,147.225 120.32,146.946 121.361,146.946 121.793,147.378 121.793,148.412 122.504,149.123 122.779,149.123 123.077,149.124 123.495,149.123 123.825,149.454 125.171,149.454 126.822,151.105 127.737,151.105 129.057,152.425 130.251,152.425 132.545,154.719 v3(134.007,154.719)
  GND02 w0.109: v1(118.865,148.165) v2(119.265,148.565)
  PWR13 w0.114: v1(118.865,148.165) v2(119.265,148.565)
  Bottom Layer w0.114: v3(134.007,154.719) J2.31@136.1,154.719
  Bottom Layer w0.254: R24.1@119.097,149.166 119.097,148.733 v2(119.265,148.565)
  other v4: 119.265,148.565
NetC28_2: C28.2 F2.2 U2.30 | length 7.7
  Top Layer w0.254: v3(123.99,145.853) 123.99,147.18 123.52,147.65 123.52,149.149 124.028,149.657 124.422,149.657 F2.2@124.625,149.86
  Bottom Layer w0.203: v3(123.99,145.853) 123.99,145.529 124.209,145.31 U2.30@124.5,145.31
  Bottom Layer w0.254: C28.2@123.546,147.52 123.99,147.075 v3(123.99,145.853)
NetC81_1: C81.1 R25.2 U19.4 U19.10 | length 6.6
  Top Layer w0.254: R25.2@124.87,153.67 C81.1@125.955,153.67 125.955,153.717 126.885,154.647 U19.10@126.885,155.345 ; U19.10@126.885,155.092 U19.10@126.885,155.345 ; U19.4@127.385,158.345 127.385,157.967 126.885,157.467 U19.10@126.885,155.345
NetC96_2: C96.2 R62.2 R64.1 U7.4 | length 3.4
  Top Layer w0.254: U7.4@130.024,168.775 v3(130.721,168.775) 131.17,168.775 C96.2@131.416,168.529
  Bottom Layer w0.254: R62.2@129.95,169.545 v3(130.721,168.775) 130.966,168.529 R64.1@131.416,168.529
NetC125_1: C125.1 C126.1 F6.2 U1.G8 | length 11.4
  Top Layer w0.254: U1.G8@116.465,153.765 v2(116.865,154.165)
  ART05 w0.178: v1(117.265,153.765) 117.665,153.365 121.437,153.365 121.837,153.765 v1(122.065,153.765)
  GND02 w0.305: v2(116.865,154.165) v1(117.265,153.765)
  PWR13 w0.178: v4(121.665,152.565) 121.665,153.365 v1(122.065,153.765)
  Bottom Layer w0.254: C126.1@121.006,151.921 121.416,151.921 121.665,152.17 v4(121.665,152.565) 121.45,152.565 121.196,152.819 C125.1@121.196,153.348 C125.1@121.198,153.346
  Bottom Layer w0.381: C125.1@121.198,153.346 F6.2@122.72,153.346
NetC134_1: C134.1 R7.2 U11.4 U11.10 | length 9.8
  ART03 w0.254: v3(125.955,160.772) 126.004,160.772 v3(127.461,159.315)
  Bottom Layer w0.254: R7.2@125.955,160.02 v3(125.955,160.772) ; v3(127.461,159.315) 126.885,158.739 U11.10@126.885,158.345 126.885,156.909 127.385,156.409 U11.4@127.385,155.345 127.385,154.145 C134.1@127.86,153.67 127.86,153.178 v3(127.99,153.048)
NetC135_1: C135.1 U10.30 | length 2.6
  Top Layer w0.254: U10.30@116.935,137.43 117.357,137.43 117.5,137.287 118.013,137.287 v3(118.089,137.363)
  Bottom Layer w0.381: C135.1@116.907,136.963 117.689,136.963 v3(118.089,137.363)
NetC140_1: C140.1 R11.2 U14.4 U14.10 | length 13.1
  Top Layer w0.254: U14.10@100.735,145.53 v9(102.367,145.53) 102.867,145.03 U14.4@103.735,145.03 ; R11.2@100.936,138.303 v3(100.936,138.944) C140.1@100.936,139.573
  ART10 w0.254: v1(100.885,145.352) 100.699,145.352 100.203,144.856 100.203,139.677 v3(100.936,138.944)
  GND02 w0.254: v1(100.885,145.352) 101.063,145.53 v9(102.367,145.53)
NetC145_2: C145.2 F7.1 U2.28 | length 9.2
  Top Layer w0.381: v3(125.247,147.244) 125.855,147.851 C145.2@125.855,147.955 F7.1@127.51,147.955
  ART05 w0.381: v3(122.339,145.853) 122.866,146.38 123.622,146.38 124.485,147.244 v3(125.247,147.244)
  Bottom Layer w0.203: v3(122.339,145.853) 122.784,145.408 122.784,144.831 122.987,144.628 123.546,144.628 123.663,144.51 U2.28@124.5,144.51
NetDONE_1: DONE.1 R35.1 U1.R11 | length 24.5
  Top Layer w0.114: v2(109.665,150.965) U1.R11@110.065,151.365
  Top Layer w0.254: R35.1@100.555,163.83 DONE.1@100.555,165.1 v3(100.555,165.852)
  GND02 w0.109: v1(109.265,150.565) v2(109.665,150.965)
  ART07 w0.119: v3(100.555,165.852) 102.399,164.008 104.165,164.008 105.842,162.331 105.842,161.087 106.35,160.579 108.128,160.579 108.89,159.817 108.89,156.388 109.677,155.6 109.677,150.977 v1(109.265,150.565)
NetG1_3: G1.3 R59.1 | length 2.2
  Top Layer w0.114: R59.1@100.886,155.353 100.886,156.182 101.035,156.331 G1.3@101.035,157.495
NetR5_2: R5.2 R8.1 U11.5 | length 3.1
  Bottom Layer w0.254: R5.2@124.87,153.67 R8.1@125.955,153.67 125.955,153.787 126.885,154.717 U11.5@126.885,155.345
NetR9_1: R9.1 R63.2 U10.31 | length 2.8
  Top Layer w0.254: U10.31@116.935,137.93 117.511,137.93 v3(117.638,137.803)
  Bottom Layer w0.381: R63.2@116.907,139.249 R9.1@116.907,138.106 117.638,138.106 ; 117.64,138.106 117.791,137.955
NetR10_2: R10.2 R12.1 U14.5 | length 15
  Top Layer w0.254: v6@103.048,145.53 U14.5@103.735,145.53 ; R10.2@103.661,138.303 R12.1@103.661,139.573 104.128,139.573 104.353,139.348 v3(104.353,139.006)
  ART03 w0.102: v6(103.048,145.517) 102.879,145.517 101.663,144.301 100.689,144.301 100.152,143.764 100.152,140.741 101.549,139.344 102.26,139.344 103.073,138.532 103.879,138.532 v3(104.353,139.006)
NetR16_1: R16.1 U1.B10 | length 2.7
  Top Layer w0.114: U1.B10@120.465,152.165 v4(120.865,152.565)
  GND02 w0.109: v4(120.865,152.565) v1(121.265,152.165)
  PWR13 w0.114: v4(120.865,152.565) v1(121.265,152.165)
  Bottom Layer w0.114: R16.1@119.917,152.692 120.738,152.692 v4(120.865,152.565)
  other v2: 120.865,152.565
NetR21_1: R21.1 U2.39 | length 2.2
  Bottom Layer w0.114: U2.39@128.4,146.01 128.4,146.637 128.854,147.091 129.188,147.091 R21.1@129.616,147.52
NetR23_2: R23.2 R26.1 U19.5 | length 3.1
  Top Layer w0.254: R23.2@126.753,159.998 R23.2@126.775,160.02 ; R23.2@126.775,159.813 R23.2@126.775,160.02 ; U19.5@126.885,158.345 126.885,158.991 126.949,159.055 126.949,159.461 126.775,159.635 R23.2@126.775,160.02 ; R26.1@127.86,160.02 R23.2@126.775,160.02
NetR28_1: R28.1 S0.1 | length 1.8
  Top Layer w0.114: S0.1@119.409,140.843 v3(120.053,141.487)
  Bottom Layer w0.114: R28.1@119.409,140.843 v3(120.053,141.487)
NetR29_1: R29.1 S1.1 | length 1.8
  Top Layer w0.114: S1.1@119.409,139.7 v3(120.053,140.344)
  Bottom Layer w0.114: R29.1@119.409,139.7 v3(120.053,140.344)
NetR36_2: R36.2 U1.R10 | length 19.3
  Top Layer w0.114: v2(109.665,152.565) v1(110.065,152.165)
  Top Layer w0.254: R36.2@103.28,165.1 v3@103.28,165.843
  GND02 w0.109: v2(109.665,152.565) v1(110.065,152.165)
  ART07 w0.119: v3(103.258,165.865) 106.192,162.931 106.639,162.931 109.677,159.893 109.677,156.743 109.855,156.566 110.312,156.566 110.465,156.413 110.465,152.565 v1(110.065,152.165)
NetR37_1: R37.1 U1.L6 | length 21.9
  Top Layer w0.114: v2(112.865,155.765) v1(113.265,155.365)
  Top Layer w0.203: v3(102.956,162.719) 102.956,163.39 103.28,163.714 R37.1@103.28,163.83
  ART05 w0.109: v3(102.956,162.719) 103.149,162.526 103.149,161.061 102.184,160.096 102.184,156.192 103.716,154.661 106.274,154.661 106.578,154.965 108.687,154.965 108.864,155.143 108.864,155.524 109.093,155.753 112.877,155.753 v1(113.265,155.365)
  GND02 w0.109: v2(112.865,155.765) v1(113.265,155.365)
NetR40_1: R40.1 U1.M6 | length 2.4
  Top Layer w0.114: v2(112.065,155.765) v1(112.465,155.365)
  GND02 w0.109: v2(112.065,155.765) v1(112.465,155.365)
  PWR13 w0.114: v1(112.465,155.365) v4(112.865,155.765)
  Bottom Layer w0.254: v4(112.865,155.765) 113.334,155.296 R40.1@113.36,155.296
NetR61_1: R61.1 U6.L8 | length 4.5
  ART12 w0.102: v8(116.586,160.02) 116.586,162.021 v1(117.1,162.535)
  PWR13 w0.114: v7(116.7,162.935) v1(117.1,162.535)
  Bottom Layer w0.114: R61.1@115.98,160.02 v8(116.586,160.02) ; U6.L8@116.3,163.335 v7(116.7,162.935)
NetR65_2: R65.2 U7.5 | length 1.6
  Top Layer w0.254: U7.5@130.024,169.275 131.019,169.275 R65.2@131.416,169.672
NetR66_1: R66.1 U8.L8 | length 14.3
  Top Layer w0.114: v1(116.3,168.135) v2(116.7,168.535)
  ART03 w0.102: v3(106.479,169.545) 107.038,170.104 116.51,170.104 116.713,169.901 116.713,168.758 116.3,168.345 v1(116.3,168.135)
  GND02 w0.102: v1(116.3,168.135) v2(116.7,168.535)
  Bottom Layer w0.114: R66.1@105.82,169.545 v3(106.479,169.545)
NetR69_2: R69.2 U1.G5 | length 2.7
  Top Layer w0.114: U1.G5@116.465,156.165 v2(116.865,156.565)
  GND02 w0.109: v2(116.865,156.565) v1(117.265,156.165)
  PWR13 w0.114: v2(116.865,156.565) v1(117.265,156.165)
  Bottom Layer w0.254: v2(116.865,156.565) 117.065,156.365 R69.2@117.065,155.643
  other v4: 116.865,156.565
NetR70_2: R70.2 U1.H5 | length 3.4
  Top Layer w0.114: U1.H5@115.665,156.165 v2(116.065,156.565)
  GND02 w0.109: v2(116.065,156.565) v1(116.465,156.165)
  PWR13 w0.114: v1(116.465,156.165) 116.865,155.765 v4(116.865,154.947)
  Bottom Layer w0.114: v4(116.865,154.947) 117.065,154.747 R70.2@117.065,154.178
NetR106_2: R106.2 U2.27 | length 6.9
  Top Layer w0.114: v3(123.19,146.907) 122.447,146.907 121.971,146.431 121.971,144.78 122.174,144.577 122.853,144.577 v3(123.228,144.202)
  Bottom Layer w0.114: R106.2@122.428,147.444 122.965,146.907 v3(123.19,146.907) ; v3(123.228,144.202) 123.32,144.11 U2.27@124.5,144.11
NetR135_2: R135.2 U12.24 | length 2.3
  Top Layer w0.114: R135.2@124.46,139.475 124.46,140.589 124.6,140.729 U12.24@124.6,141.76
NetR136_1: R136.1 U12.22 | length 7.5
  Top Layer w0.114: v3(122.568,140.322) 123.241,140.995 123.241,141.961 124.04,142.76 U12.22@124.6,142.76
  ART12 w0.102: v3(122.568,140.322) 123.825,139.065 v8(125.07,139.065)
  Bottom Layer w0.114: v8(125.07,139.065) 125.32,139.065 R136.1@125.73,139.475
PG_1V0: U10.28 U15.1 | length 16
  Top Layer w0.254: U10.28@116.935,136.43 117.714,136.43 v3(117.816,136.328)
  ART03 w0.381: v3(104.95,137.344) 110.23,137.344 111.811,135.763 115.722,135.763 116.287,136.328 v3(117.816,136.328)
  Bottom Layer w0.381: v3(104.95,137.344) 105.395,136.899 U15.1@105.395,136.255
PG_1V5: U11.11 | length 1
  Bottom Layer w0.254: v3(127.385,157.334) U11.11@127.385,158.345
PG_1V8: U14.11 U16.1 | length 40.5
  Top Layer w0.254: U14.11@100.735,145.03 102.1,145.03 v6(102.877,144.254)
  ART03 w0.305: v1(101.575,143.942) 102.159,143.942 102.471,144.254 v6(102.877,144.254)
  ART05 w0.109: v1(101.575,143.942) 100.914,143.942 100.178,144.678 100.178,152.222 100.609,152.654 103.276,152.654 103.861,153.238 106.528,153.238 108.56,151.206 116.332,151.206 116.891,151.765 122.174,151.765 123.247,152.838 v3(124.498,152.838)
  Bottom Layer w0.254: v3(124.498,152.838) 124.784,152.838 125.08,152.542 U16.1@125.08,152.13
PG_3V3: U19.11 | length 1.2
  Top Layer w0.254: U19.11@127.385,155.345 127.385,154.777 127.673,154.489 v3(127.927,154.489)
PHY_LED0: R13.2 U2.32 | length 2.1
  Bottom Layer w0.114: R13.2@124.612,147.52 124.816,147.316 124.816,147.111 125.089,146.837 125.428,146.837 v4(125.6,146.666) U2.32@125.6,146.01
